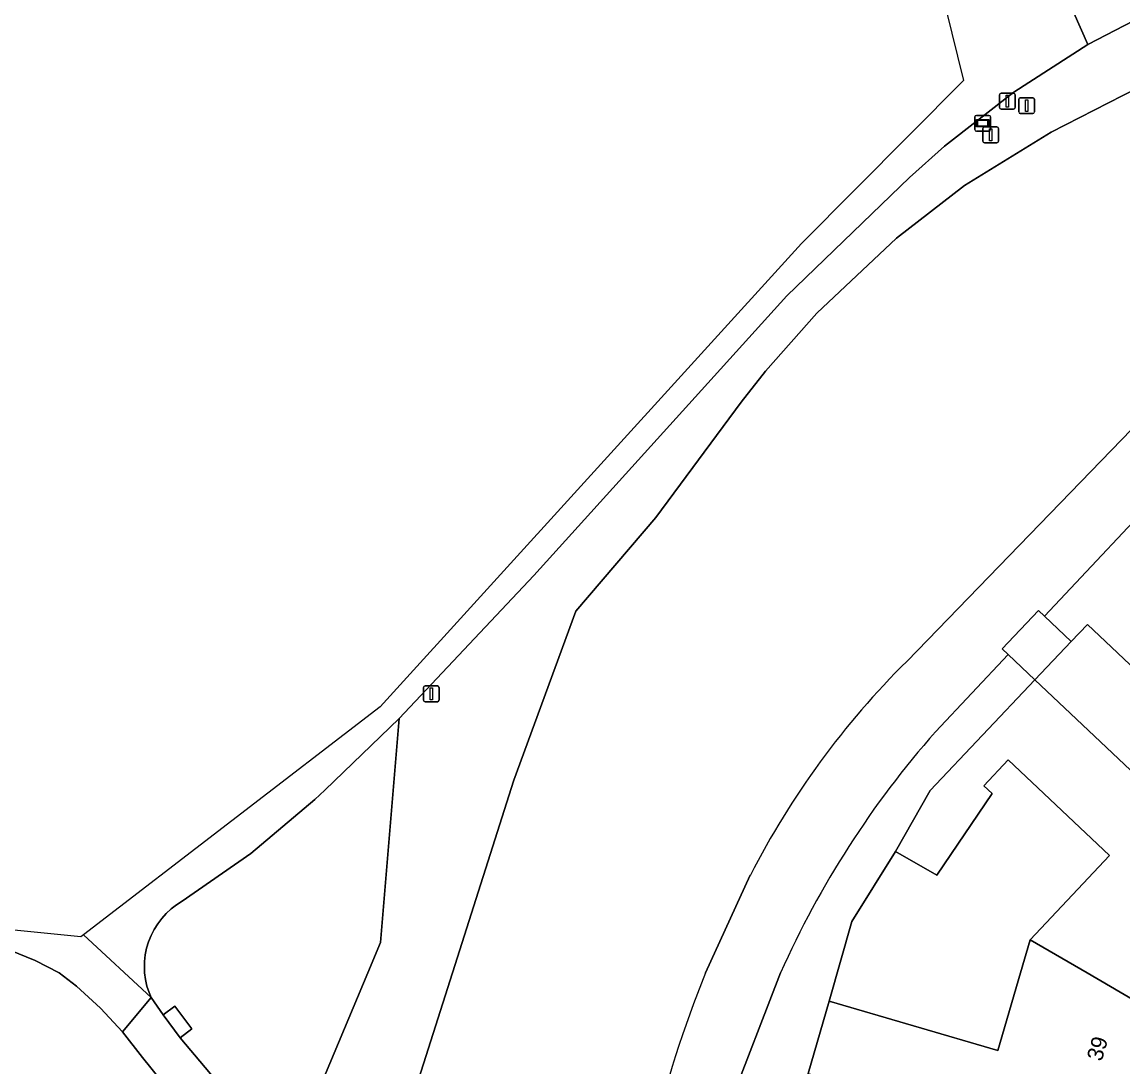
# Model space of a CAD drawing. Extents: x 158472 to 159562, y 388525 to 389606.
# Drawn here: x 158786.9 to 158856.4, y 389244.1 to 389310.1 of the extents above; entities that cross this region are included whole.
import ezdxf

# ---------------------------------------------------------------- set-up
doc = ezdxf.new("R2010")
doc.units = 0
for name, color, linetype in [('IMGEO_Afsluitpaal', 7, 'Continuous'), ('IMGEO_Erf', 7, 'Continuous'), ('IMGEO_Fietspad_gesloten', 7, 'Continuous'), ('IMGEO_Grasland_overig', 7, 'Continuous'), ('IMGEO_Groenvoorziening', 7, 'Continuous'), ('IMGEO_Lichtmast', 7, 'Continuous'), ('IMGEO_Loofbos', 7, 'Continuous'), ('IMGEO_Pand', 7, 'Continuous'), ('IMGEO_Pand_nummerreeks', 7, 'Continuous'), ('IMGEO_Terreindeel_open', 7, 'Continuous'), ('IMGEO_Wegwijzer', 7, 'Continuous')]:
    doc.layers.add(name, color=color, linetype=linetype)

msp = doc.modelspace()

# ---------------------------------------------------------------- linework, layer by layer
at = {"layer": 'IMGEO_Afsluitpaal'}
for p, q in [((158849.834, 389304.418), (158849.834, 389305.218)), ((158849.834, 389305.218), (158849.834, 389304.418)), ((158849.934, 389305.318), (158850.724, 389305.318)), ((158850.724, 389305.318), (158849.934, 389305.318)), ((158850.824, 389305.218), (158850.824, 389304.418)), ((158850.824, 389304.418), (158850.824, 389305.218)), ((158850.724, 389304.318), (158849.934, 389304.318)), ((158849.934, 389304.318), (158850.724, 389304.318)), ((158847.569, 389302.57), (158847.569, 389303.37)), ((158847.569, 389303.37), (158847.569, 389302.57)), ((158847.669, 389303.47), (158848.459, 389303.47)), ((158848.459, 389303.47), (158847.669, 389303.47)), ((158848.559, 389303.37), (158848.559, 389302.57)), ((158848.559, 389302.57), (158848.559, 389303.37)), ((158848.459, 389302.47), (158847.669, 389302.47)), ((158847.669, 389302.47), (158848.459, 389302.47))]:
    msp.add_line(p, q, dxfattribs=at)
for points in [[(158850.254, 389305.193), (158850.404, 389305.193), (158850.404, 389304.443), (158850.254, 389304.443), (158850.254, 389305.193)], [(158847.989, 389303.345), (158848.139, 389303.345), (158848.139, 389302.595), (158847.989, 389302.595), (158847.989, 389303.345)]]:
    msp.add_lwpolyline(points, dxfattribs=at)
for centre, start, end in [((158849.934, 389305.218), 90, 180), ((158849.934, 389305.218), 90, 180), ((158850.724, 389305.218), 0, 90), ((158850.724, 389305.218), 360, 90), ((158849.934, 389304.418), 180, 270), ((158849.934, 389304.418), 180, 270), ((158850.724, 389304.418), 270, 0), ((158850.724, 389304.418), 270, 0), ((158847.669, 389303.37), 90, 180), ((158847.669, 389303.37), 90, 180), ((158848.459, 389303.37), 0, 90), ((158848.459, 389303.37), 360, 90), ((158847.669, 389302.57), 180, 270), ((158847.669, 389302.57), 180, 270), ((158848.459, 389302.57), 270, 0), ((158848.459, 389302.57), 270, 0)]:
    msp.add_arc(centre, 0.1, start, end, dxfattribs=at)
at = {"layer": 'IMGEO_Erf'}
for points in [[(158861.33, 389279.576), (158861.871, 389280.148), (158860.153, 389281.769), (158859.696, 389281.316), (158851.454, 389272.556), (158853.151, 389270.949), (158854.176, 389272.032), (158862.184, 389264.451), (158865.751, 389268.22), (158869.331, 389272.001)], [(158842.044, 389257.68), (158839.3, 389253.26), (158837.864, 389248.209), (158848.518, 389245.103), (158849.947, 389250), (158850.559, 389252.102), (158855.565, 389257.425), (158849.17, 389263.48), (158847.632, 389261.818), (158848.162, 389261.339), (158844.667, 389256.188)]]:
    msp.add_lwpolyline(points, close=True, dxfattribs=at)
at = {"layer": 'IMGEO_Fietspad_gesloten'}
for points in [[(158842.263, 389323.01), (158846.356, 389306.409), (158836.102, 389296.111), (158809.486, 389266.816), (158790.748, 389252.413), (158795.028, 389248.439), (158794.894, 389248.763), (158794.765, 389249.167), (158794.673, 389249.58), (158794.618, 389250), (158794.602, 389250.307), (158794.612, 389250.731), (158794.66, 389251.152), (158794.745, 389251.568), (158794.867, 389251.974), (158795.025, 389252.368), (158795.218, 389252.746), (158795.443, 389253.105), (158795.7, 389253.443), (158795.986, 389253.756), (158796.298, 389254.043), (158796.635, 389254.301), (158796.994, 389254.527), (158801.33, 389257.557), (158805.378, 389260.962), (158806.006, 389261.549), (158810.693, 389266.089), (158819.21, 389275.122), (158835.18, 389292.8), (158842.932, 389300.27), (158845.14, 389302.25), (158849.522, 389305.67), (158854.192, 389308.684), (158852.84, 389311.805)], [(158864.431, 389317.967), (158852.84, 389311.805), (158854.192, 389308.684), (158879.636, 389321.9)], [(158786.102, 389251.439), (158787.694, 389250.789), (158789.221, 389250), (158790.308, 389249.158), (158791.832, 389247.784), (158793.226, 389246.28), (158795.028, 389248.439), (158790.748, 389252.413), (158790.589, 389252.291), (158758.589, 389255.493)], [(158801.597, 389240.269), (158796.87, 389245.903), (158795.785, 389247.346), (158795.028, 389248.439), (158793.226, 389246.28), (158794.481, 389244.657), (158795.62, 389243.234)]]:
    msp.add_lwpolyline(points, dxfattribs=at)
at = {"layer": 'IMGEO_Grasland_overig'}
for points in [[(158850.856, 389268.526), (158849.168, 389270.125), (158844.575, 389265.244)], [(158820.266, 389194.664), (158816.423, 389191.171), (158820.07, 389192.695), (158820.756, 389191.056), (158823.646, 389191.469), (158825.135, 389192.324), (158825.986, 389192.595), (158826.881, 389192.371), (158825.927, 389195.028), (158824.185, 389199.854), (158824.342, 389202.243), (158830.829, 389224.285), (158832.209, 389229.018), (158835.171, 389238.974), (158836.533, 389243.644), (158837.864, 389248.209), (158839.3, 389253.26), (158842.044, 389257.68), (158844.233, 389261.53), (158847.54, 389265.023), (158850.856, 389268.526)], [(158834.789, 389250), (158831.522, 389241.543), (158822.979, 389207.946), (158821.471, 389201.566)]]:
    msp.add_lwpolyline(points, dxfattribs=at)
msp.add_arc((158889.487, 389225.649), 59.873, 138.60041, 156.00211, dxfattribs=at)
at = {"layer": 'IMGEO_Groenvoorziening'}
for points in [[(158879.636, 389321.9), (158854.192, 389308.684), (158849.522, 389305.67), (158845.14, 389302.25), (158842.932, 389300.27), (158835.18, 389292.8), (158819.21, 389275.122), (158810.693, 389266.089), (158809.514, 389251.925), (158808.711, 389250), (158803.538, 389237.63)], [(158805.829, 389224.162), (158814.064, 389250), (158817.947, 389262.183), (158821.864, 389272.876), (158826.902, 389278.783), (158832.299, 389286.076), (158833.845, 389288.035), (158837.087, 389291.696), (158842.123, 389296.446), (158846.408, 389299.763), (158851.882, 389303.138), (158863.655, 389309.163)], [(158864.705, 389292.361), (158842.78, 389269.713)], [(158844.575, 389265.244), (158849.168, 389270.125), (158848.788, 389270.485), (158851.082, 389272.908), (158851.454, 389272.556), (158859.696, 389281.316), (158860.153, 389281.769), (158860.08, 389281.838), (158862.63, 389284.541), (158862.796, 389284.384), (158867.292, 389288.833)], [(158832.88, 389256.184), (158830.045, 389250)], [(158781.047, 389216.631), (158789.248, 389221.931), (158794.781, 389228.33), (158796.029, 389231.036), (158798.432, 389229.928), (158803.356, 389223.351), (158803.225, 389227.524), (158803.084, 389229.372), (158802.779, 389231.199), (158802.312, 389232.992), (158801.687, 389234.736), (158800.908, 389236.418), (158800.751, 389236.715), (158795.62, 389243.234), (158794.481, 389244.657), (158793.226, 389246.28), (158791.832, 389247.784), (158790.308, 389249.158), (158789.221, 389250), (158787.694, 389250.789), (158786.102, 389251.439)], [(158821.471, 389201.566), (158822.979, 389207.946), (158831.522, 389241.543), (158834.789, 389250)]]:
    msp.add_lwpolyline(points, dxfattribs=at)
for centre, radius, start, end in [((158880.418, 389231.784), 53.434, 134.77955, 152.83), ((158889.487, 389225.649), 59.873, 138.60041, 156.00211), ((158897.191, 389222.877), 72.417, 158.00399, 166.82456)]:
    msp.add_arc(centre, radius, start, end, dxfattribs=at)
at = {"layer": 'IMGEO_Lichtmast'}
for p, q in [((158848.622, 389304.7), (158848.622, 389305.5)), ((158848.622, 389305.5), (158848.622, 389304.7)), ((158848.722, 389305.6), (158849.512, 389305.6)), ((158849.512, 389305.6), (158848.722, 389305.6)), ((158849.612, 389305.5), (158849.612, 389304.7)), ((158849.612, 389304.7), (158849.612, 389305.5)), ((158849.512, 389304.6), (158848.722, 389304.6)), ((158848.722, 389304.6), (158849.512, 389304.6)), ((158812.229, 389267.244), (158812.229, 389268.044)), ((158812.229, 389268.044), (158812.229, 389267.244)), ((158812.329, 389268.144), (158813.119, 389268.144)), ((158813.119, 389268.144), (158812.329, 389268.144)), ((158813.219, 389268.044), (158813.219, 389267.244)), ((158813.219, 389267.244), (158813.219, 389268.044)), ((158813.119, 389267.144), (158812.329, 389267.144)), ((158812.329, 389267.144), (158813.119, 389267.144))]:
    msp.add_line(p, q, dxfattribs=at)
for points in [[(158849.042, 389305.475), (158849.192, 389305.475), (158849.192, 389304.725), (158849.042, 389304.725), (158849.042, 389305.475)], [(158812.649, 389268.019), (158812.799, 389268.019), (158812.799, 389267.269), (158812.649, 389267.269), (158812.649, 389268.019)]]:
    msp.add_lwpolyline(points, dxfattribs=at)
for centre, start, end in [((158848.722, 389305.5), 90, 180), ((158848.722, 389305.5), 90, 180), ((158849.512, 389305.5), 0, 90), ((158849.512, 389305.5), 360, 90), ((158848.722, 389304.7), 180, 270), ((158848.722, 389304.7), 180, 270), ((158849.512, 389304.7), 270, 0), ((158849.512, 389304.7), 270, 0), ((158812.329, 389268.044), 90, 180), ((158812.329, 389268.044), 90, 180), ((158813.119, 389268.044), 0, 90), ((158813.119, 389268.044), 360, 90), ((158812.329, 389267.244), 180, 270), ((158812.329, 389267.244), 180, 270), ((158813.119, 389267.244), 270, 0), ((158813.119, 389267.244), 270, 0)]:
    msp.add_arc(centre, 0.1, start, end, dxfattribs=at)
at = {"layer": 'IMGEO_Loofbos'}
for points in [[(158863.655, 389309.163), (158851.882, 389303.138), (158846.408, 389299.763), (158842.123, 389296.446), (158837.087, 389291.696), (158833.845, 389288.035), (158832.299, 389286.076), (158826.902, 389278.783), (158821.864, 389272.876), (158817.947, 389262.183), (158814.064, 389250), (158805.829, 389224.162)], [(158842.78, 389269.713), (158864.705, 389292.361)], [(158803.538, 389237.63), (158808.711, 389250), (158809.514, 389251.925), (158810.693, 389266.089), (158806.006, 389261.549), (158805.378, 389260.962), (158801.33, 389257.557), (158796.994, 389254.527), (158796.635, 389254.301), (158796.298, 389254.043), (158795.986, 389253.756), (158795.7, 389253.443), (158795.443, 389253.105), (158795.218, 389252.746), (158795.025, 389252.368), (158794.867, 389251.974), (158794.745, 389251.568), (158794.66, 389251.152), (158794.612, 389250.731), (158794.602, 389250.307), (158794.618, 389250), (158794.673, 389249.58), (158794.765, 389249.167), (158794.894, 389248.763), (158795.028, 389248.439), (158795.785, 389247.346), (158796.521, 389247.899), (158797.592, 389246.467), (158796.87, 389245.903), (158801.597, 389240.269)], [(158830.045, 389250), (158832.88, 389256.184)]]:
    msp.add_lwpolyline(points, dxfattribs=at)
for centre, radius, start, end in [((158880.418, 389231.784), 53.434, 134.77955, 152.83), ((158897.191, 389222.877), 72.417, 158.00399, 166.82456)]:
    msp.add_arc(centre, radius, start, end, dxfattribs=at)
at = {"layer": 'IMGEO_Pand'}
for points in [[(158853.151, 389270.949), (158851.454, 389272.556), (158851.082, 389272.908), (158848.788, 389270.485), (158849.168, 389270.125), (158850.856, 389268.526)], [(158865.751, 389268.22), (158862.184, 389264.451), (158854.176, 389272.032), (158853.151, 389270.949), (158850.856, 389268.526), (158870.46, 389250), (158871.053, 389249.44), (158871.583, 389250), (158873.585, 389252.115), (158868.045, 389257.359), (158872.354, 389261.91)], [(158850.856, 389268.526), (158847.54, 389265.023), (158844.233, 389261.53), (158842.044, 389257.68), (158844.667, 389256.188), (158848.162, 389261.339), (158847.632, 389261.818), (158849.17, 389263.48), (158855.565, 389257.425), (158850.559, 389252.102), (158854.151, 389250), (158858.584, 389247.406), (158858.62, 389247.53), (158860.959, 389250), (158862.808, 389251.953), (158864.871, 389250), (158868.411, 389246.649), (158871.053, 389249.44), (158870.46, 389250)], [(158863.137, 389235.745), (158864.158, 389239.247), (158856.828, 389241.384), (158858.584, 389247.406), (158854.151, 389250), (158850.559, 389252.102), (158849.947, 389250), (158848.518, 389245.103), (158837.864, 389248.209), (158836.533, 389243.644)]]:
    msp.add_lwpolyline(points, close=True, dxfattribs=at)
at = {"layer": 'IMGEO_Terreindeel_open'}
msp.add_lwpolyline([(158796.87, 389245.903), (158797.592, 389246.467), (158796.521, 389247.899), (158795.785, 389247.346)], close=True, dxfattribs=at)
at = {"layer": 'IMGEO_Wegwijzer'}
for p, q in [((158847.061, 389303.303), (158847.061, 389304.103)), ((158847.061, 389304.103), (158847.061, 389303.303)), ((158847.161, 389304.203), (158847.951, 389304.203)), ((158847.951, 389304.203), (158847.161, 389304.203)), ((158848.051, 389304.103), (158848.051, 389303.303)), ((158848.051, 389303.303), (158848.051, 389304.103)), ((158847.951, 389303.203), (158847.161, 389303.203)), ((158847.161, 389303.203), (158847.951, 389303.203))]:
    msp.add_line(p, q, dxfattribs=at)
for points in [[(158847.162, 389303.935), (158847.95, 389303.935), (158847.95, 389303.471), (158847.162, 389303.471), (158847.162, 389303.935)], [(158847.227, 389303.87), (158847.227, 389303.536), (158847.885, 389303.536), (158847.885, 389303.87), (158847.227, 389303.87)]]:
    msp.add_lwpolyline(points, dxfattribs=at)
for centre, start, end in [((158847.161, 389304.103), 90, 180), ((158847.161, 389304.103), 90, 180), ((158847.951, 389304.103), 0, 90), ((158847.951, 389304.103), 360, 90), ((158847.161, 389303.303), 180, 270), ((158847.161, 389303.303), 180, 270), ((158847.951, 389303.303), 270, 0), ((158847.951, 389303.303), 270, 0)]:
    msp.add_arc(centre, 0.1, start, end, dxfattribs=at)

# ---------------------------------------------------------------- texts
at = {"layer": 'IMGEO_Pand_nummerreeks'}
msp.add_text('39', height=1, rotation=73.74481, dxfattribs=at).set_placement((158855.073, 389244.37))

doc.saveas('drawing.dxf')
